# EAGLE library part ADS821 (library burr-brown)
10-Bit, 40 MSPS ADC SE/Diff Inputs with Int References and 9.3 bit ENOB
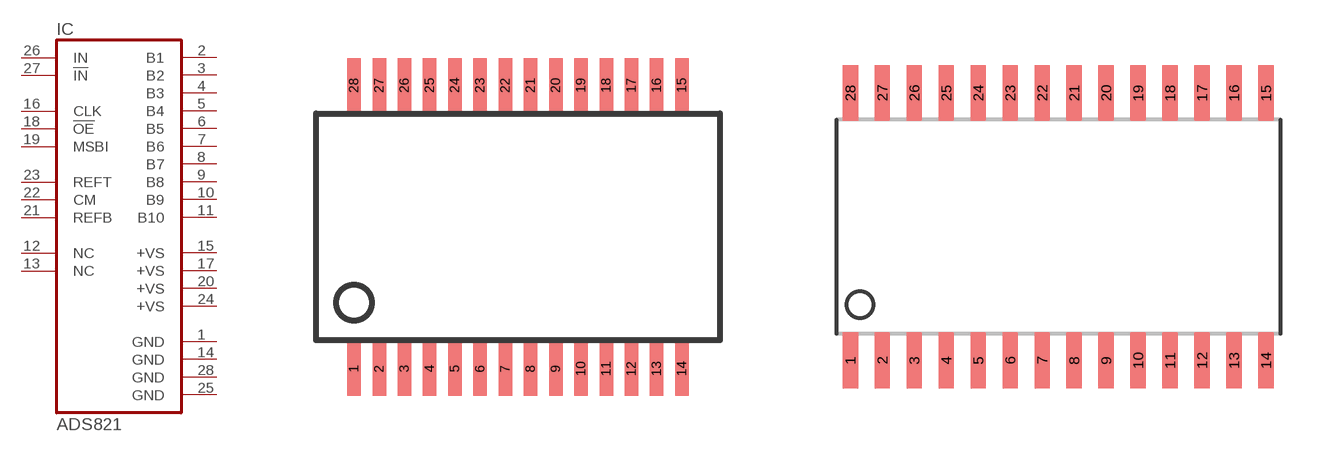
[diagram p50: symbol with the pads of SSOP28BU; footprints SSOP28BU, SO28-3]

Designator prefix IC

## ADS821E (OC_FARNELL: unknown; OC_NEWARK: unknown)  [SSOP28BU]
1  GND  pwr
2  B1  out
3  B2  out
4  B3  out
5  B4  out
6  B5  out
7  B6  out
8  B7  out
9  B8  out
10  B9  out
11  B10  out
12  NC  nc
13  NC  nc
14  GND  pwr
15  +VS  pwr
16  CLK  in
17  +VS  pwr
18  !OE  in
19  MSBI  in
20  +VS  pwr
21  REFB  in
22  CM  in
23  REFT  in
24  +VS  pwr
25  GND  pwr
26  IN  in
27  !IN  in
28  GND  pwr

## ADS821U (MF: TEXAS INSTRUMENT CONNECTORS; MPN: ADS821U; OC_FARNELL: 1509519; OC_NEWARK: 35C1575)  [SO28-3]
1  GND  pwr
2  B1  out
3  B2  out
4  B3  out
5  B4  out
6  B5  out
7  B6  out
8  B7  out
9  B8  out
10  B9  out
11  B10  out
12  NC  nc
13  NC  nc
14  GND  pwr
15  +VS  pwr
16  CLK  in
17  +VS  pwr
18  !OE  in
19  MSBI  in
20  +VS  pwr
21  REFB  in
22  CM  in
23  REFT  in
24  +VS  pwr
25  GND  pwr
26  IN  in
27  !IN  in
28  GND  pwr

## Footprint SSOP28BU (pad centres in mm)
Small Shrink Outline Package
smd 0.348 x 1.397: 1 -4.225,-3.656; 2 -3.575,-3.656; 3 -2.925,-3.656; 4 -2.275,-3.656; 5 -1.625,-3.656; 6 -0.975,-3.656; 7 -0.325,-3.656; 8 0.325,-3.656; 9 0.975,-3.656; 10 1.625,-3.656; 11 2.275,-3.656; 12 2.925,-3.656; 13 3.575,-3.656; 14 4.225,-3.656; 15 4.225,3.656; 16 3.575,3.656; 17 2.925,3.656; 18 2.275,3.656; 19 1.625,3.656; 20 0.975,3.656; 21 0.325,3.656; 22 -0.325,3.656; 23 -0.975,3.656; 24 -1.625,3.656; 25 -2.275,3.656; 26 -2.925,3.656; 27 -3.575,3.656; 28 -4.225,3.656

## Footprint SO28-3 (pad centres in mm)
Small Outline Package
smd 0.61 x 2.21: 1 -8.255,-5.315; 2 -6.985,-5.315; 3 -5.715,-5.315; 4 -4.445,-5.315; 5 -3.175,-5.315; 6 -1.905,-5.315; 7 -0.635,-5.315; 8 0.635,-5.315; 9 1.905,-5.315; 10 3.175,-5.315; 11 4.445,-5.315; 12 5.715,-5.315; 13 6.985,-5.315; 14 8.255,-5.315; 15 8.255,5.315; 16 6.985,5.315; 17 5.715,5.315; 18 4.445,5.315; 19 3.175,5.315; 20 1.905,5.315; 21 0.635,5.315; 22 -0.635,5.315; 23 -1.905,5.315; 24 -3.175,5.315; 25 -4.445,5.315; 26 -5.715,5.315; 27 -6.985,5.315; 28 -8.255,5.315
